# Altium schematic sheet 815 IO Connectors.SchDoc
size Letter; Organization: Toradex Solutions Inc.; Address1: 6415 Northwest Drive; Address2: Mississauga, ON, L4V 1X1; Address3: Canada
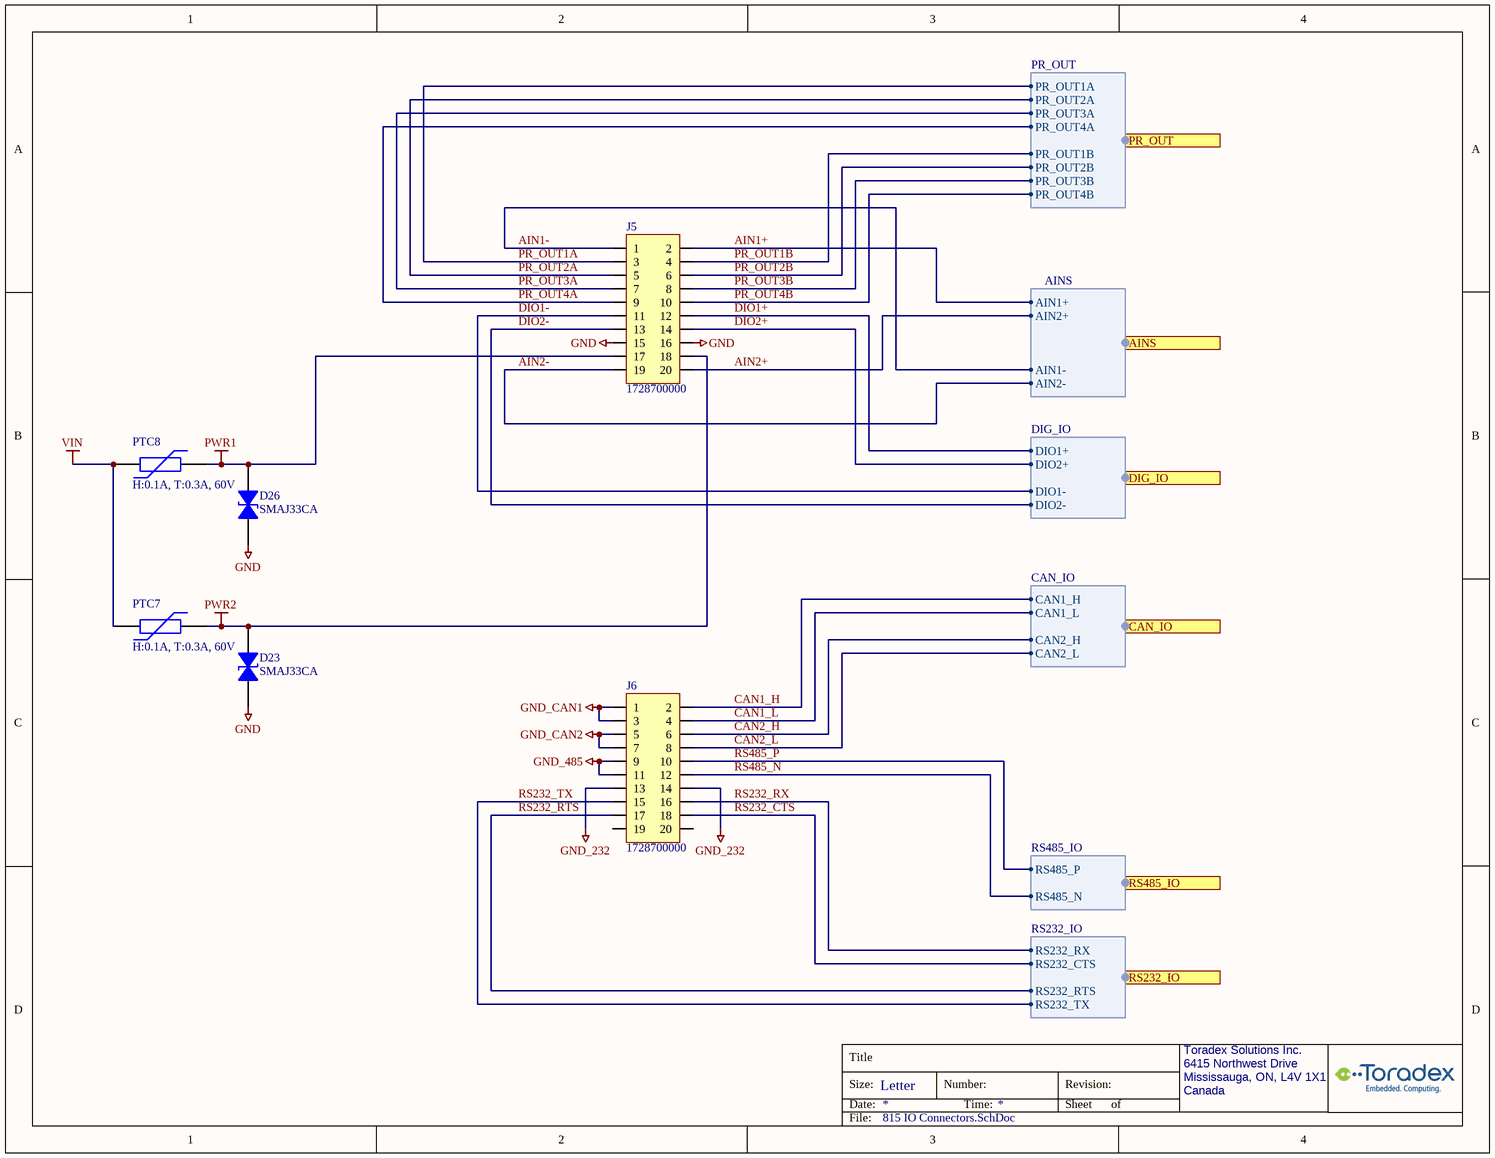
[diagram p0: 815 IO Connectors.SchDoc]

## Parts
D23  SMAJ33CA  [SMAJ_TRANSIL]
D26  SMAJ33CA  [SMAJ_TRANSIL]
J5  1728700000  [WEIDMULLER_1728700000]
J6  1728700000  [WEIDMULLER_1728700000]
PTC7  H:0.1A, T:0.3A, 60V  [PTC_1812]
PTC8  H:0.1A, T:0.3A, 60V  [PTC_1812]

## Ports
AINS (harness AINS), CAN_IO (harness CAN_IO), DIG_IO (harness DIG_IO), PR_OUT (harness PR_OUT), RS232_IO (harness RS232_IO), RS485_IO (harness RS485_IO)

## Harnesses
PR_OUT: PR_OUT1A, PR_OUT1B, PR_OUT2A, PR_OUT2B, PR_OUT3A, PR_OUT3B, PR_OUT4A, PR_OUT4B
DIG_IO: DIO1+, DIO1-, DIO2+, DIO2-
AINS: AIN1+, AIN1-, AIN2+, AIN2-
CAN_IO: CAN2_H, CAN2_L, CAN1_H, CAN1_L
RS232_IO: RS232_RX, RS232_CTS, RS232_TX, RS232_RTS
RS485_IO: RS485_N, RS485_P

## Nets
GND: D23.2 D26.2 J5.15 J5.16
GND_232: J6.13 J6.14
GND_485: J6.9 J6.11
GND_CAN1: J6.1 J6.3
GND_CAN2: J6.5 J6.7
PWR1: D26.1 J5.17 PTC8.2
PWR2: D23.1 J5.18 PTC7.2
VIN: PTC7.1 PTC8.1
AIN1+: J5.2 ; port AINS.AIN1+
AIN1-: J5.1 ; port AINS.AIN1-
AIN2+: J5.20 ; port AINS.AIN2+
AIN2-: J5.19 ; port AINS.AIN2-
CAN1_H: J6.2 ; port CAN_IO.CAN1_H
CAN1_L: J6.4 ; port CAN_IO.CAN1_L
CAN2_H: J6.6 ; port CAN_IO.CAN2_H
CAN2_L: J6.8 ; port CAN_IO.CAN2_L
DIO1+: J5.12 ; port DIG_IO.DIO1+
DIO1-: J5.11 ; port DIG_IO.DIO1-
DIO2+: J5.14 ; port DIG_IO.DIO2+
DIO2-: J5.13 ; port DIG_IO.DIO2-
PR_OUT1A: J5.3 ; port PR_OUT.PR_OUT1A
PR_OUT1B: J5.4 ; port PR_OUT.PR_OUT1B
PR_OUT2A: J5.5 ; port PR_OUT.PR_OUT2A
PR_OUT2B: J5.6 ; port PR_OUT.PR_OUT2B
PR_OUT3A: J5.7 ; port PR_OUT.PR_OUT3A
PR_OUT3B: J5.8 ; port PR_OUT.PR_OUT3B
PR_OUT4A: J5.9 ; port PR_OUT.PR_OUT4A
PR_OUT4B: J5.10 ; port PR_OUT.PR_OUT4B
RS232_CTS: J6.18 ; port RS232_IO.RS232_CTS
RS232_RTS: J6.17 ; port RS232_IO.RS232_RTS
RS232_RX: J6.16 ; port RS232_IO.RS232_RX
RS232_TX: J6.15 ; port RS232_IO.RS232_TX
RS485_N: J6.12 ; port RS485_IO.RS485_N
RS485_P: J6.10 ; port RS485_IO.RS485_P

Not connected (* = marked no-connect by the designer): J6 19 20

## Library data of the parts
D23 D26 = 0581-SMAJ33CA: (-55 to 150 DegC) TVS DIODE 33VWM Vbrm:36.7V Vcl:53.3V 400W SMA; MfrNo: SMAJ33CA-E3/5A; Mfr: Vishay Semiconductor Diodes Division; PN: 581; Desc: (-55 to 150 DegC) TVS DIODE 33VWM Vbrm:36.7V Vstd:53.3VC SMA; Alt: SMAJ33CA-E3/61GICT-ND; Alt2: SMAJ33CABCT-ND; DR: SMAJ33CA-E3/5AGIDKR-ND; DR2: 625-SMAJ33CA-E3/5A
J5 J6 = 2319-Conn-Hdr-2x10pin-RA-Flanges: (-50 to 100 DegC) TERM BLOCK HDR 20POS 90DEG 3.5MM; Mfr: Weidmuller; PN: 2319
PTC7 PTC8 = 1423-PTC-0.1A-60V-1812: (-40 to 85 DegC) PTC Ih:0.1A, It:0.3A, 60V, 1812, 1.6-15ohm; MfrNo: 0ZCG0010FF2C; Mfr: Bel; PN: 1423; Alt: MPTS1812L010R,MPTS1812L010,1812L010/60DR,PTSA181260V010,MF-MSMF010-2,PFMF.010.2,MINISMDC010F-2,MINIASMDC010F-2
